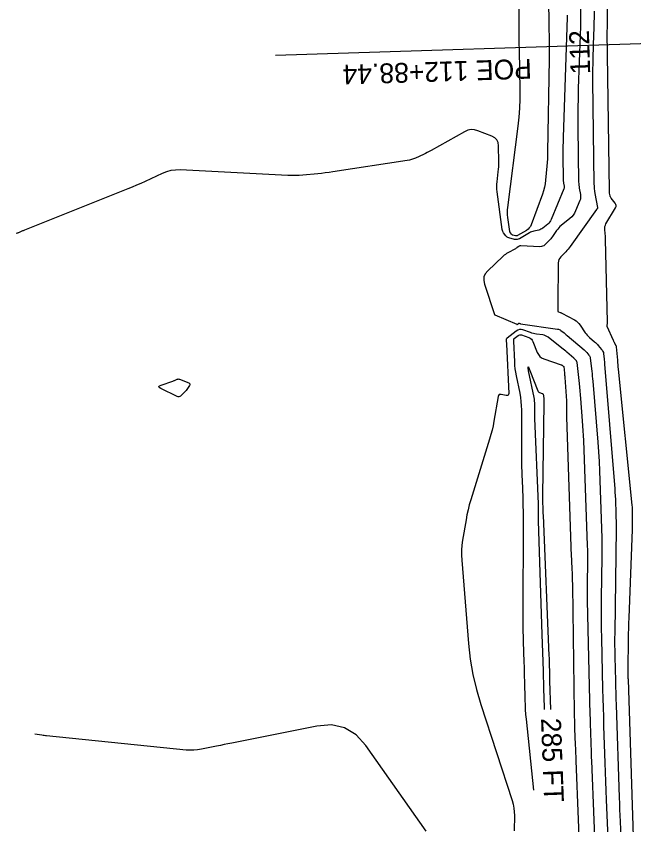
# Model space of a CAD drawing. Extents: x 1768942 to 1774819, y 723037 to 732099.
# Drawn here: x 1770600.2 to 1770787.1, y 725288.6 to 725533.3 of the extents above; entities that cross this region are included whole.
import ezdxf

# ---------------------------------------------------------------- set-up
doc = ezdxf.new("R2010")
doc.units = 0
for name, color, linetype in [('R_Contour Annot', 7, 'Continuous'), ('R_Contours', 7, 'Continuous'), ('R_Horz Alg', 7, 'Continuous'), ('R_Horz Alg Annot', 7, 'Continuous')]:
    doc.layers.add(name, color=color, linetype=linetype)

msp = doc.modelspace()

# ---------------------------------------------------------------- linework, layer by layer
at = {"layer": 'R_Contours'}
for points in [[(1770760.96, 725545.79), (1770761.37, 725533.07), (1770761.45, 725529.88), (1770761.49, 725526.7), (1770761.5, 725523.52), (1770761.47, 725520.34), (1770761.05, 725492.31), (1770761.03, 725491.23), (1770760.98, 725490.15), (1770760.91, 725489.07), (1770760.82, 725487.99), (1770760.41, 725483.68), (1770760.28, 725482.61), (1770760.08, 725481.56), (1770759.81, 725480.52), (1770759.47, 725479.49), (1770756.06, 725470.19), (1770755.82, 725469.68), (1770755.5, 725469.23), (1770755.11, 725468.84), (1770754.65, 725468.51), (1770751.93, 725466.93), (1770751.77, 725466.86), (1770751.61, 725466.82), (1770751.45, 725466.81), (1770751.27, 725466.84), (1770750.48, 725467.04), (1770750.36, 725467.08), (1770750.26, 725467.14), (1770750.17, 725467.21), (1770750.08, 725467.31), (1770749.78, 725467.71), (1770749.72, 725467.81), (1770749.66, 725467.92), (1770749.62, 725468.04), (1770749.6, 725468.16), (1770749.02, 725472.45), (1770748.94, 725473.2), (1770748.91, 725473.96), (1770748.93, 725474.72), (1770749, 725475.47), (1770752.14, 725500.05), (1770752.44, 725502.78), (1770752.64, 725505.51), (1770752.74, 725508.25), (1770752.73, 725511), (1770752.5, 725523.03), (1770752.47, 725525.26), (1770752.44, 725527.49), (1770752.43, 725529.71), (1770752.44, 725531.94), (1770752.47, 725541.76)], [(1770787.08, 725284.99), (1770785.47, 725332.57), (1770785.46, 725332.81), (1770785.45, 725333.05), (1770785.45, 725333.3), (1770785.44, 725333.54), (1770785.42, 725334.51), (1770785.41, 725334.75), (1770785.41, 725334.99), (1770785.41, 725335.23), (1770785.41, 725335.48), (1770785.53, 725344.74), (1770785.56, 725346.37), (1770785.59, 725347.99), (1770785.64, 725349.62), (1770785.69, 725351.24), (1770786.68, 725377.97), (1770786.7, 725378.58), (1770786.71, 725379.19), (1770786.73, 725379.8), (1770786.74, 725380.41), (1770786.77, 725382.85), (1770786.77, 725383.46), (1770786.75, 725384.07), (1770786.71, 725384.68), (1770786.66, 725385.28), (1770782.49, 725426.49), (1770782.43, 725427.17), (1770782.36, 725427.85), (1770782.3, 725428.53), (1770782.25, 725429.21), (1770781.92, 725433.25), (1770781.91, 725433.27), (1770781.91, 725433.29), (1770781.91, 725433.31), (1770781.91, 725433.33), (1770781.9, 725433.4), (1770781.9, 725433.42), (1770781.89, 725433.43), (1770781.88, 725433.45), (1770781.87, 725433.46), (1770781.78, 725433.57), (1770781.76, 725433.59), (1770781.75, 725433.61), (1770781.73, 725433.64), (1770781.72, 725433.66), (1770781.26, 725434.52), (1770781.18, 725434.68), (1770781.11, 725434.83), (1770781.03, 725434.98), (1770780.96, 725435.14), (1770779.11, 725439.36), (1770779.07, 725439.48), (1770779.05, 725439.59), (1770779.05, 725439.72), (1770779.06, 725439.84), (1770779.17, 725440.33), (1770779.19, 725440.45), (1770779.2, 725440.58), (1770779.21, 725440.7), (1770779.21, 725440.83), (1770778.57, 725465.71), (1770778.55, 725466.11), (1770778.54, 725466.52), (1770778.51, 725466.92), (1770778.48, 725467.32), (1770778.34, 725468.94), (1770778.34, 725469.33), (1770778.4, 725469.72), (1770778.51, 725470.09), (1770778.69, 725470.44), (1770781.62, 725475.37), (1770781.77, 725475.71), (1770781.8, 725476.04), (1770781.72, 725476.37), (1770781.53, 725476.69), (1770780.26, 725478.29), (1770780.16, 725478.44), (1770780.07, 725478.61), (1770780, 725478.78), (1770779.95, 725478.97), (1770779.81, 725479.72), (1770779.78, 725479.91), (1770779.76, 725480.1), (1770779.74, 725480.29), (1770779.73, 725480.48), (1770779.1, 725528.64), (1770779.1, 725528.75), (1770779.1, 725528.86), (1770779.1, 725528.98), (1770779.1, 725529.09), (1770779.12, 725529.54), (1770779.12, 725529.65), (1770779.13, 725529.76), (1770779.13, 725529.87), (1770779.13, 725529.99), (1770779.16, 725545.69)], [(1770771.03, 725535.46), (1770770.99, 725532.85), (1770770.94, 725530.24), (1770770.86, 725527.63), (1770770.33, 725511.46), (1770770.25, 725508.53), (1770770.2, 725505.61), (1770770.19, 725502.68), (1770770.21, 725499.75), (1770770.43, 725483.13), (1770770.45, 725482.66), (1770770.48, 725482.18), (1770770.54, 725481.71), (1770770.62, 725481.24), (1770770.97, 725479.36), (1770771.03, 725478.89), (1770771.02, 725478.44), (1770770.94, 725477.98), (1770770.79, 725477.54), (1770769.49, 725474.38), (1770769.17, 725473.73), (1770768.79, 725473.14), (1770768.33, 725472.6), (1770767.8, 725472.11), (1770765.17, 725469.97), (1770764.78, 725469.63), (1770764.42, 725469.27), (1770764.08, 725468.88), (1770763.77, 725468.47), (1770762.47, 725466.64), (1770762.22, 725466.29), (1770761.96, 725465.96), (1770761.68, 725465.65), (1770761.38, 725465.34), (1770760.18, 725464.13), (1770759.86, 725463.87), (1770759.52, 725463.69), (1770759.14, 725463.59), (1770758.73, 725463.57), (1770752.89, 725463.83), (1770752.73, 725463.82), (1770752.59, 725463.79), (1770752.45, 725463.74), (1770752.31, 725463.66), (1770751.8, 725463.29), (1770751.67, 725463.2), (1770751.54, 725463.12), (1770751.41, 725463.04), (1770751.27, 725462.96), (1770749.04, 725461.75), (1770748.63, 725461.51), (1770748.24, 725461.25), (1770747.87, 725460.96), (1770747.52, 725460.64), (1770742.9, 725456.25), (1770742.18, 725455.37), (1770741.77, 725454.41), (1770741.68, 725453.38), (1770741.9, 725452.26), (1770744.98, 725442.99), (1770744.98, 725442.98), (1770744.98, 725442.98), (1770744.99, 725442.96), (1770744.99, 725442.95), (1770744.99, 725442.95), (1770744.99, 725442.95), (1770745, 725442.95), (1770745.04, 725442.93), (1770745.06, 725442.92), (1770751.67, 725440.08), (1770751.75, 725440.05), (1770751.82, 725440.05), (1770751.89, 725440.07), (1770751.95, 725440.11), (1770752.26, 725440.35), (1770752.3, 725440.37), (1770752.34, 725440.38), (1770752.39, 725440.38), (1770752.43, 725440.37), (1770752.62, 725440.31), (1770752.67, 725440.29), (1770752.71, 725440.28), (1770752.76, 725440.27), (1770752.81, 725440.26), (1770764.03, 725438.65), (1770764.31, 725438.59), (1770764.58, 725438.49), (1770764.84, 725438.36), (1770765.08, 725438.2), (1770766.01, 725437.46), (1770766.24, 725437.28), (1770766.47, 725437.09), (1770766.7, 725436.9), (1770766.93, 725436.71), (1770772.12, 725432.31), (1770772.32, 725432.13), (1770772.51, 725431.95), (1770772.69, 725431.76), (1770772.87, 725431.56), (1770773.56, 725430.77), (1770773.71, 725430.56), (1770773.83, 725430.33), (1770773.91, 725430.1), (1770773.96, 725429.84), (1770774.4, 725425.86), (1770774.48, 725425.11), (1770774.55, 725424.35), (1770774.62, 725423.6), (1770774.69, 725422.85), (1770776.19, 725404.36), (1770776.41, 725401.47), (1770776.6, 725398.57), (1770776.75, 725395.68), (1770776.87, 725392.78), (1770777.29, 725381.18), (1770777.37, 725378.28), (1770777.42, 725375.38), (1770777.44, 725372.48), (1770777.42, 725369.58), (1770777.26, 725357.19), (1770777.24, 725354.16), (1770777.24, 725351.13), (1770777.27, 725348.1), (1770777.32, 725345.06), (1770777.68, 725329.65), (1770777.75, 725326.85), (1770777.83, 725324.06), (1770777.91, 725321.26), (1770778, 725318.47), (1770778.38, 725307.29), (1770778.48, 725304.5), (1770778.58, 725301.7), (1770778.68, 725298.91), (1770778.79, 725296.12), (1770779.44, 725279.88)], [(1770775.09, 725534.82), (1770775.08, 725533.06), (1770775.05, 725531.31), (1770775.02, 725529.55), (1770774.96, 725527.79), (1770774.73, 725520.75), (1770774.68, 725518.99), (1770774.66, 725517.23), (1770774.65, 725515.48), (1770774.66, 725513.72), (1770775.07, 725482.61), (1770775.1, 725481.88), (1770775.15, 725481.14), (1770775.24, 725480.42), (1770775.36, 725479.69), (1770776.17, 725475.42), (1770776.17, 725475.39), (1770776.17, 725475.35), (1770776.17, 725475.32), (1770776.16, 725475.28), (1770776.1, 725475.15), (1770776.09, 725475.12), (1770776.07, 725475.09), (1770776.04, 725475.06), (1770776.02, 725475.04), (1770775.9, 725474.94), (1770775.88, 725474.92), (1770775.85, 725474.89), (1770775.83, 725474.87), (1770775.8, 725474.84), (1770767.88, 725463.62), (1770767.56, 725463.2), (1770767.23, 725462.79), (1770766.88, 725462.39), (1770766.52, 725462.01), (1770765.02, 725460.51), (1770764.69, 725460.11), (1770764.46, 725459.68), (1770764.31, 725459.21), (1770764.26, 725458.7), (1770764.1, 725446.2), (1770764.1, 725445.97), (1770764.1, 725445.75), (1770764.1, 725445.52), (1770764.1, 725445.29), (1770764.09, 725444.19), (1770764.11, 725444.07), (1770764.15, 725443.98), (1770764.23, 725443.9), (1770764.34, 725443.85), (1770764.84, 725443.69), (1770764.97, 725443.64), (1770765.09, 725443.59), (1770765.21, 725443.54), (1770765.32, 725443.48), (1770769.13, 725441.41), (1770769.65, 725441.09), (1770770.11, 725440.72), (1770770.53, 725440.29), (1770770.9, 725439.8), (1770772.42, 725437.53), (1770772.7, 725437.14), (1770773, 725436.78), (1770773.32, 725436.44), (1770773.67, 725436.12), (1770775.25, 725434.79), (1770775.54, 725434.53), (1770775.82, 725434.26), (1770776.1, 725433.98), (1770776.36, 725433.69), (1770777.39, 725432.49), (1770777.62, 725432.18), (1770777.8, 725431.85), (1770777.92, 725431.5), (1770777.99, 725431.13), (1770778.15, 725429.59), (1770778.2, 725429.21), (1770778.23, 725428.82), (1770778.27, 725428.44), (1770778.3, 725428.05), (1770781.28, 725391.48), (1770781.36, 725390.38), (1770781.43, 725389.28), (1770781.49, 725388.18), (1770781.54, 725387.07), (1770781.69, 725382.65), (1770781.73, 725381.55), (1770781.75, 725380.45), (1770781.75, 725379.34), (1770781.74, 725378.24), (1770781.34, 725346.69), (1770781.33, 725344.87), (1770781.33, 725343.06), (1770781.35, 725341.25), (1770781.38, 725339.43), (1770781.55, 725332.18), (1770781.59, 725330.37), (1770781.64, 725328.56), (1770781.69, 725326.74), (1770781.75, 725324.93), (1770782.71, 725296.79), (1770782.77, 725294.98), (1770782.84, 725293.18), (1770782.9, 725291.37), (1770782.97, 725289.57), (1770783.26, 725282.35)], [(1770766.96, 725533.67), (1770766.94, 725532.96), (1770765.74, 725496.67), (1770765.7, 725495.32), (1770765.68, 725493.98), (1770765.68, 725492.63), (1770765.69, 725491.29), (1770765.79, 725483.66), (1770765.79, 725483.44), (1770765.81, 725483.22), (1770765.84, 725483), (1770765.87, 725482.78), (1770766.04, 725481.92), (1770766.06, 725481.71), (1770766.06, 725481.5), (1770766.02, 725481.29), (1770765.95, 725481.09), (1770762.13, 725471.8), (1770761.93, 725471.41), (1770761.7, 725471.05), (1770761.42, 725470.72), (1770761.1, 725470.42), (1770759.62, 725469.21), (1770759.32, 725469), (1770759.01, 725468.83), (1770758.68, 725468.69), (1770758.33, 725468.59), (1770756.9, 725468.28), (1770756.55, 725468.18), (1770756.2, 725468.06), (1770755.87, 725467.92), (1770755.55, 725467.75), (1770752.51, 725465.98), (1770752.16, 725465.82), (1770751.8, 725465.73), (1770751.43, 725465.72), (1770751.05, 725465.78), (1770749.27, 725466.23), (1770749.01, 725466.32), (1770748.77, 725466.44), (1770748.57, 725466.61), (1770748.38, 725466.82), (1770747.71, 725467.72), (1770747.56, 725467.96), (1770747.44, 725468.2), (1770747.35, 725468.46), (1770747.3, 725468.74), (1770745.73, 725480.2), (1770745.66, 725480.96), (1770745.63, 725481.71), (1770745.65, 725482.47), (1770745.72, 725483.22), (1770746.11, 725486.24), (1770746.19, 725487), (1770746.25, 725487.75), (1770746.27, 725488.51), (1770746.27, 725489.27), (1770746.18, 725494.1), (1770746.04, 725495.07), (1770745.66, 725495.88), (1770745.03, 725496.52), (1770744.17, 725496.99), (1770739.9, 725498.65), (1770738.86, 725498.94), (1770737.85, 725498.99), (1770736.85, 725498.8), (1770735.87, 725498.37), (1770725.76, 725492.66), (1770725.19, 725492.35), (1770724.61, 725492.04), (1770724.03, 725491.76), (1770723.43, 725491.48), (1770721.05, 725490.41), (1770720.45, 725490.16), (1770719.84, 725489.96), (1770719.21, 725489.8), (1770718.57, 725489.68), (1770696, 725486.2), (1770694.87, 725486.04), (1770693.75, 725485.89), (1770692.62, 725485.76), (1770691.48, 725485.64), (1770686.95, 725485.21), (1770685.82, 725485.12), (1770684.69, 725485.08), (1770683.55, 725485.07), (1770682.42, 725485.11), (1770649.77, 725486.78), (1770648.37, 725486.77), (1770647, 725486.59), (1770645.66, 725486.24), (1770644.35, 725485.73), (1770639.19, 725483.32), (1770637.9, 725482.73), (1770636.59, 725482.16), (1770635.28, 725481.6), (1770633.97, 725481.06), (1770602.7, 725468.57), (1770602.5, 725468.49), (1770602.3, 725468.4), (1770602.1, 725468.32), (1770601.91, 725468.23), (1770600.85, 725467.76), (1770600.78, 725467.73), (1770600.72, 725467.71), (1770600.65, 725467.68), (1770600.58, 725467.66), (1770600.18, 725467.52)], [(1770775.83, 725271.98), (1770774.4, 725307.9), (1770774.35, 725309.06), (1770774.31, 725310.23), (1770774.27, 725311.4), (1770774.23, 725312.56), (1770774.07, 725317.23), (1770774.03, 725318.39), (1770774, 725319.56), (1770773.97, 725320.73), (1770773.94, 725321.89), (1770773.14, 725356.42), (1770773.11, 725357.81), (1770773.1, 725359.19), (1770773.1, 725360.58), (1770773.11, 725361.97), (1770773.18, 725367.53), (1770773.19, 725368.92), (1770773.18, 725370.31), (1770773.16, 725371.7), (1770773.12, 725373.09), (1770771.98, 725404.87), (1770771.91, 725406.37), (1770771.83, 725407.87), (1770771.74, 725409.38), (1770771.62, 725410.88), (1770771.07, 725417.64), (1770770.98, 725418.77), (1770770.87, 725419.89), (1770770.76, 725421), (1770770.64, 725422.12), (1770769.94, 725428.56), (1770769.91, 725428.69), (1770769.87, 725428.82), (1770769.81, 725428.93), (1770769.73, 725429.03), (1770769.38, 725429.44), (1770769.29, 725429.54), (1770769.2, 725429.64), (1770769.1, 725429.73), (1770769, 725429.82), (1770766.89, 725431.61), (1770766.51, 725431.93), (1770766.12, 725432.25), (1770765.73, 725432.57), (1770765.33, 725432.88), (1770761.21, 725436.13), (1770760.83, 725436.39), (1770760.42, 725436.6), (1770759.99, 725436.75), (1770759.54, 725436.84), (1770757.67, 725437.11), (1770757.21, 725437.19), (1770756.75, 725437.29), (1770756.3, 725437.41), (1770755.85, 725437.55), (1770753.52, 725438.35), (1770753, 725438.47), (1770752.5, 725438.45), (1770752.01, 725438.31), (1770751.55, 725438.03), (1770748.75, 725435.9), (1770748.64, 725435.79), (1770748.56, 725435.67), (1770748.51, 725435.53), (1770748.51, 725435.38), (1770748.54, 725434.73), (1770748.55, 725434.57), (1770748.56, 725434.41), (1770748.56, 725434.25), (1770748.57, 725434.09), (1770749.26, 725419.14), (1770749.23, 725418.8), (1770749.09, 725418.59), (1770748.86, 725418.49), (1770748.52, 725418.51), (1770746.97, 725418.85), (1770746.62, 725418.87), (1770746.35, 725418.78), (1770746.16, 725418.56), (1770746.06, 725418.23), (1770744.78, 725410.76), (1770744.52, 725409.39), (1770744.22, 725408.03), (1770743.88, 725406.68), (1770743.49, 725405.34), (1770737.78, 725386.93), (1770737.34, 725385.44), (1770736.96, 725383.94), (1770736.63, 725382.43), (1770736.34, 725380.9), (1770735.31, 725374.78), (1770735.1, 725373.25), (1770734.98, 725371.71), (1770734.97, 725370.17), (1770735.05, 725368.63), (1770737.12, 725343.44), (1770737.64, 725338.76), (1770738.43, 725334.12), (1770739.49, 725329.54), (1770740.82, 725325.02), (1770750.29, 725295.89), (1770750.6, 725294.78), (1770750.82, 725293.65), (1770750.95, 725292.51), (1770750.99, 725291.35), (1770750.96, 725286.7)], [(1770756.85, 725299.05), (1770754.62, 725320.57), (1770754.48, 725322.01), (1770754.38, 725323.44), (1770754.3, 725324.88), (1770754.25, 725326.31), (1770754.11, 725332.07), (1770754.08, 725333.51), (1770754.04, 725334.94), (1770754, 725336.38), (1770753.95, 725337.82), (1770753.75, 725344.01), (1770753.71, 725345.53), (1770753.68, 725347.04), (1770753.66, 725348.55), (1770753.66, 725350.06), (1770753.7, 725382.25), (1770753.7, 725383.57), (1770753.68, 725384.9), (1770753.64, 725386.22), (1770753.6, 725387.55), (1770753.39, 725392.85), (1770753.34, 725394.17), (1770753.3, 725395.5), (1770753.28, 725396.82), (1770753.27, 725398.15), (1770753.22, 725414.19), (1770753.18, 725415.44), (1770753.08, 725416.69), (1770752.92, 725417.94), (1770752.7, 725419.18), (1770751.61, 725424.5), (1770751.41, 725425.54), (1770751.26, 725426.59), (1770751.15, 725427.64), (1770751.08, 725428.7), (1770750.8, 725434.92), (1770750.79, 725434.99), (1770750.79, 725435.06), (1770750.79, 725435.14), (1770750.78, 725435.21), (1770750.77, 725435.51), (1770750.77, 725435.58), (1770750.79, 725435.64), (1770750.83, 725435.7), (1770750.88, 725435.74), (1770752.11, 725436.68), (1770752.35, 725436.82), (1770752.59, 725436.9), (1770752.84, 725436.9), (1770753.1, 725436.84), (1770755.33, 725436.08), (1770755.75, 725435.89), (1770756.11, 725435.62), (1770756.39, 725435.27), (1770756.6, 725434.86), (1770757.9, 725431.53), (1770758.23, 725430.89), (1770758.67, 725430.36), (1770759.22, 725429.94), (1770759.88, 725429.64), (1770765.14, 725427.85), (1770765.21, 725427.82), (1770765.28, 725427.79), (1770765.35, 725427.75), (1770765.41, 725427.71), (1770765.74, 725427.45), (1770765.76, 725427.43), (1770765.77, 725427.42), (1770765.78, 725427.41), (1770765.8, 725427.4), (1770765.88, 725427.33), (1770765.88, 725427.33), (1770765.89, 725427.32), (1770765.9, 725427.3), (1770765.91, 725427.3), (1770765.91, 725427.3), (1770765.91, 725427.29), (1770765.91, 725427.29), (1770766.13, 725425.32), (1770766.16, 725424.99), (1770766.19, 725424.66), (1770766.22, 725424.33), (1770766.25, 725424), (1770766.74, 725416.9), (1770766.77, 725416.49), (1770766.79, 725416.07), (1770766.79, 725415.66), (1770766.79, 725415.24), (1770766.77, 725413.58), (1770766.76, 725413.17), (1770766.77, 725412.75), (1770766.77, 725412.34), (1770766.78, 725411.93), (1770768.21, 725369.82), (1770768.24, 725369.08), (1770768.27, 725368.33), (1770768.3, 725367.58), (1770768.33, 725366.84), (1770768.45, 725363.85), (1770768.48, 725363.11), (1770768.51, 725362.36), (1770768.52, 725361.61), (1770768.54, 725360.87), (1770769.08, 725322.56), (1770769.1, 725321.34), (1770769.13, 725320.12), (1770769.17, 725318.9), (1770769.21, 725317.68), (1770769.39, 725312.79), (1770769.43, 725311.57), (1770769.48, 725310.35), (1770769.53, 725309.12), (1770769.58, 725307.9), (1770770.97, 725272.4)], [(1770760.07, 725323.44), (1770760.05, 725324.23), (1770759.91, 725329.72), (1770759.76, 725335.22), (1770759.6, 725340.71), (1770759.43, 725346.21), (1770758.31, 725380.56), (1770758.3, 725380.99), (1770758.29, 725381.42), (1770758.28, 725381.85), (1770758.28, 725382.28), (1770758.28, 725384), (1770758.28, 725384.43), (1770758.28, 725384.86), (1770758.27, 725385.28), (1770758.25, 725385.71), (1770757.21, 725411.52), (1770757.2, 725412.05), (1770757.18, 725412.58), (1770757.17, 725413.12), (1770757.17, 725413.65), (1770757.16, 725415.78), (1770757.15, 725416.32), (1770757.1, 725416.85), (1770757.04, 725417.37), (1770756.94, 725417.9), (1770755.28, 725425.98), (1770755.13, 725426.85), (1770755.14, 725427.16), (1770755.32, 725426.91), (1770755.66, 725426.1), (1770758.07, 725419.93), (1770758.15, 725419.76), (1770758.27, 725419.62), (1770758.42, 725419.5), (1770758.59, 725419.43), (1770759.35, 725419.17), (1770759.52, 725419.09), (1770759.64, 725418.97), (1770759.72, 725418.82), (1770759.76, 725418.64), (1770759.85, 725417.3), (1770759.87, 725417.01), (1770759.88, 725416.72), (1770759.89, 725416.43), (1770759.89, 725416.14), (1770759.48, 725388.39), (1770759.48, 725387.89), (1770759.48, 725387.38), (1770759.49, 725386.88), (1770759.5, 725386.38), (1770759.57, 725384.36), (1770759.59, 725383.86), (1770759.61, 725383.35), (1770759.63, 725382.85), (1770759.65, 725382.34), (1770761.45, 725339.73), (1770761.48, 725339.1), (1770761.5, 725338.48), (1770761.51, 725337.85), (1770761.53, 725337.22), (1770761.56, 725334.71), (1770761.57, 725334.08), (1770761.59, 725333.45), (1770761.6, 725332.83), (1770761.63, 725332.2), (1770761.95, 725323.51)], [(1770724.26, 725286.61), (1770706.05, 725312.54), (1770703.07, 725315.84), (1770699.6, 725317.93), (1770695.65, 725318.81), (1770691.21, 725318.48), (1770665.44, 725313.32), (1770664.29, 725313.09), (1770663.14, 725312.86), (1770661.99, 725312.62), (1770660.84, 725312.39), (1770656.25, 725311.43), (1770655.1, 725311.24), (1770653.94, 725311.14), (1770652.78, 725311.12), (1770651.62, 725311.2), (1770609.39, 725315.51), (1770609.03, 725315.55), (1770608.67, 725315.59), (1770608.31, 725315.64), (1770607.96, 725315.7), (1770605.82, 725316.05)]]:
    msp.add_lwpolyline(points, dxfattribs=at)
msp.add_lwpolyline([(1770647.79, 725422.97), (1770647.96, 725423.03), (1770648.12, 725423.1), (1770648.28, 725423.16), (1770648.92, 725423.45), (1770649.08, 725423.5), (1770649.25, 725423.52), (1770649.41, 725423.51), (1770649.57, 725423.46), (1770652.4, 725422.35), (1770652.66, 725422.2), (1770652.78, 725422.01), (1770652.78, 725421.78), (1770652.64, 725421.51), (1770651.8, 725420.35), (1770651.59, 725420.08), (1770651.38, 725419.82), (1770651.15, 725419.56), (1770650.92, 725419.32), (1770649.95, 725418.36), (1770649.7, 725418.17), (1770649.44, 725418.08), (1770649.16, 725418.08), (1770648.86, 725418.19), (1770643.95, 725420.64), (1770643.49, 725420.94), (1770643.35, 725421.22), (1770643.53, 725421.47), (1770644.03, 725421.7), (1770647.63, 725422.91)], close=True, dxfattribs=at)
at = {"layer": 'R_Horz Alg'}
msp.add_lwpolyline([(1770798.66, 725525.31), (1770678.72, 725521.48)], dxfattribs=at)

# ---------------------------------------------------------------- texts
at = {"layer": 'R_Contour Annot'}
msp.add_text('285 FT', height=6, rotation=272.1261, dxfattribs=at).set_placement((1770759.04, 725320.82))
at = {"layer": 'R_Horz Alg Annot'}
for s, rotation, p in [('112', 91.8304, (1770773.95, 725515.83)), ('112', 91.8304, (1770773.95, 725515.83)), ('POE 112+88.44', 181.8304, (1770756.17, 725520.45))]:
    msp.add_text(s, height=6, rotation=rotation, dxfattribs=at).set_placement(p)

doc.saveas('drawing.dxf')
